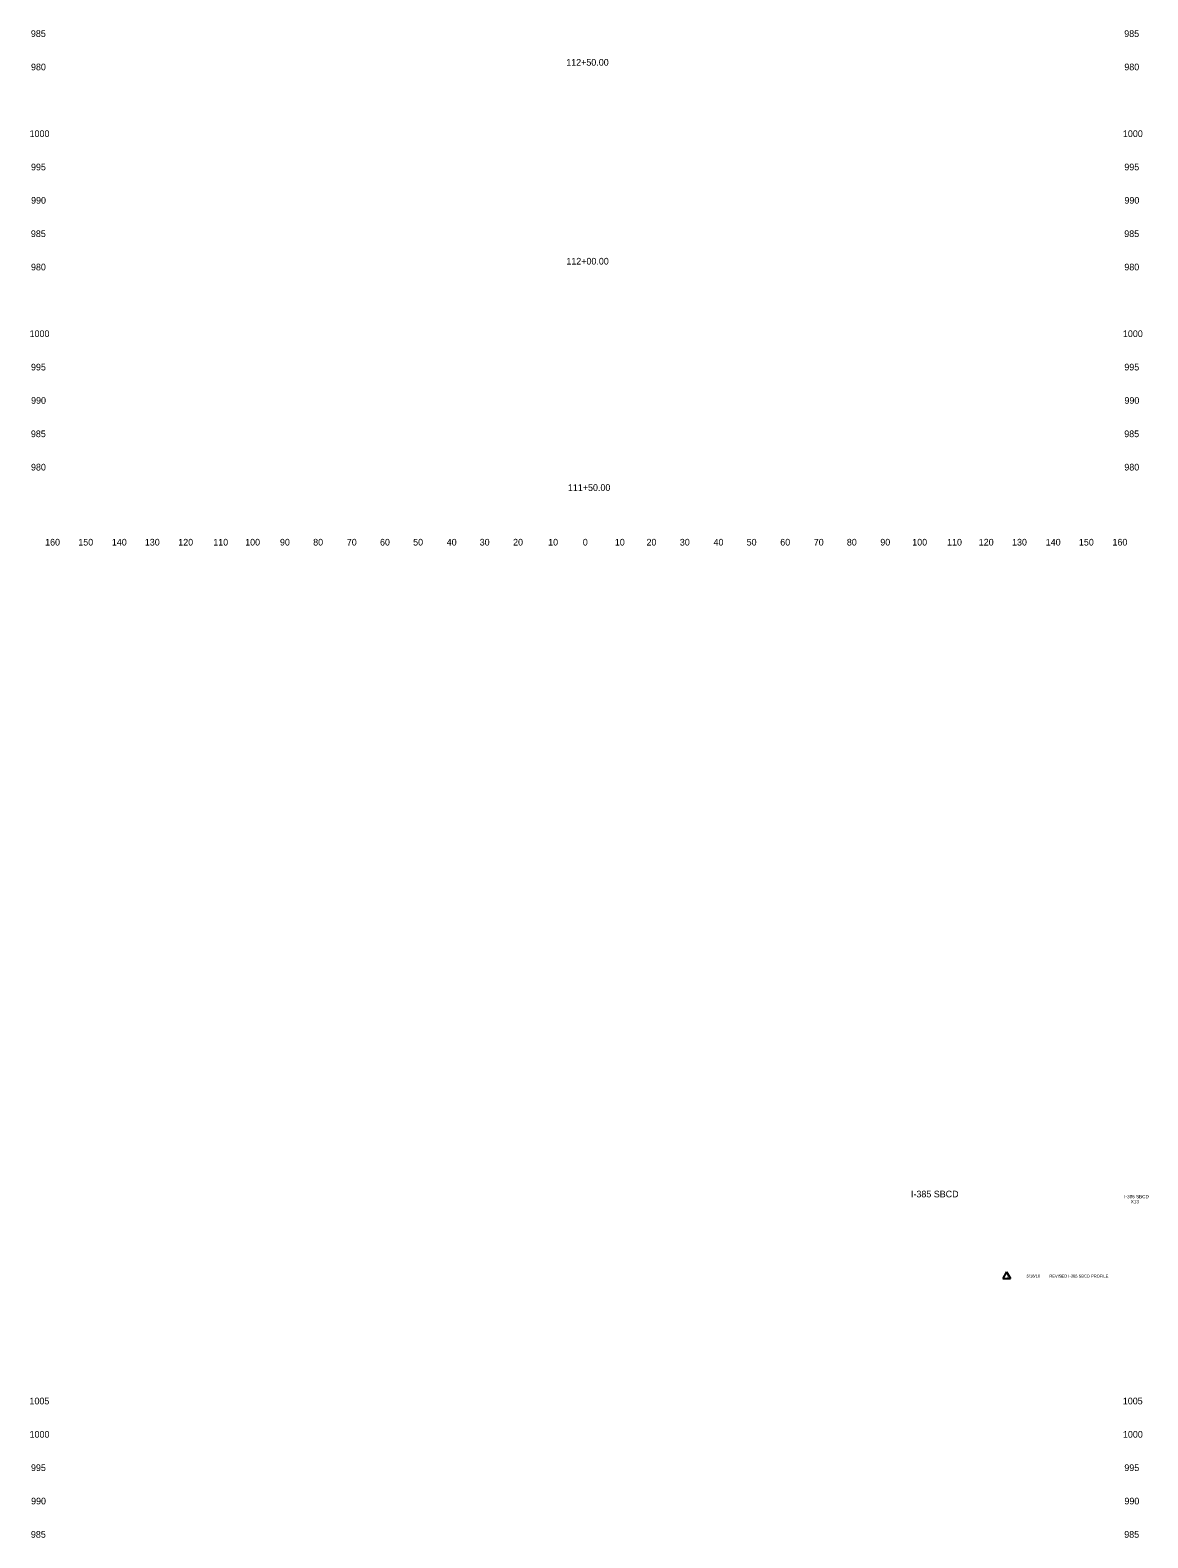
# Model space of a CAD drawing. Extents: x 4994 to 6876, y 4997 to 8804.
# Drawn here: x 5508.6 to 5843.7, y 5900 to 6352 of the extents above; entities that cross this region are included whole.
import ezdxf

# ---------------------------------------------------------------- set-up
doc = ezdxf.new("R2010")
doc.units = 0
for name, color, linetype in [('RD_SHT_ID', 7, 'Continuous'), ('RD_SHT_TX', 7, 'Continuous'), ('RD_XS_TX_Offset', 7, 'Continuous'), ('RD_XS_TX_Station', 7, 'Continuous')]:
    doc.layers.add(name, color=color, linetype=linetype)

msp = doc.modelspace()

# ---------------------------------------------------------------- linework, layer by layer
at = {"layer": 'RD_SHT_TX'}
for p, q in [((5801.37, 5979.75), (5800.23, 5977.72)), ((5800.23, 5977.72), (5802.51, 5977.72)), ((5801.37, 5979.75), (5802.51, 5977.72))]:
    msp.add_line(p, q, dxfattribs=at)

# ---------------------------------------------------------------- texts
at = {"layer": 'RD_SHT_ID'}
for s, height, p in [('I-385 SBCD', 2, (5772.69, 6002.06)), ('I-385 SBCD', 1, (5836.63, 6001.8)), ('X13', 1, (5838.57, 6000.3))]:
    msp.add_text(s, height=height, dxfattribs=at).set_placement(p)
at = {"layer": 'RD_SHT_TX'}
for s, p in [('1', (5801.37, 5978.05)), ('5/16/16', (5807.34, 5978.01)), ('REVISED I-385 SBCD PROFILE', (5814.17, 5978.01))]:
    msp.add_text(s, height=0.88, dxfattribs=at).set_placement(p)
at = {"layer": 'RD_XS_TX_Offset'}
for s, p in [('985', (5508.83, 6350)), ('985', (5836.63, 6350)), ('980', (5508.86, 6340)), ('980', (5836.66, 6340)), ('1000', (5508.44, 6320)), ('1000', (5836.24, 6320)), ('995', (5508.86, 6310)), ('995', (5836.66, 6310)), ('990', (5508.89, 6300)), ('990', (5836.69, 6300)), ('985', (5508.83, 6290)), ('985', (5836.63, 6290)), ('980', (5508.86, 6280)), ('980', (5836.66, 6280)), ('1000', (5508.44, 6260)), ('1000', (5836.24, 6260)), ('995', (5508.86, 6250)), ('995', (5836.66, 6250)), ('990', (5508.89, 6240)), ('990', (5836.69, 6240)), ('985', (5508.83, 6230)), ('985', (5836.63, 6230)), ('980', (5508.86, 6220)), ('980', (5836.66, 6220)), ('160', (5513.1, 6197.5)), ('150', (5523.04, 6197.5)), ('140', (5533.1, 6197.5)), ('130', (5542.99, 6197.5)), ('120', (5553.01, 6197.5)), ('110', (5563.51, 6197.5)), ('100', (5573.07, 6197.5)), ('90', (5583.5, 6197.5)), ('80', (5593.46, 6197.5)), ('70', (5603.54, 6197.5)), ('60', (5613.5, 6197.5)), ('50', (5623.43, 6197.5)), ('40', (5633.5, 6197.5)), ('30', (5643.39, 6197.5)), ('20', (5653.4, 6197.5)), ('10', (5663.91, 6197.5)), ('0', (5674.3, 6197.5)), ('0', (5674.3, 6197.5)), ('10', (5683.91, 6197.5)), ('20', (5693.4, 6197.5)), ('30', (5703.39, 6197.5)), ('40', (5713.5, 6197.5)), ('50', (5723.43, 6197.5)), ('60', (5733.5, 6197.5)), ('70', (5743.54, 6197.5)), ('80', (5753.46, 6197.5)), ('90', (5763.5, 6197.5)), ('100', (5773.07, 6197.5)), ('110', (5783.51, 6197.5)), ('120', (5793.01, 6197.5)), ('130', (5802.99, 6197.5)), ('140', (5813.1, 6197.5)), ('150', (5823.04, 6197.5)), ('160', (5833.1, 6197.5)), ('1005', (5508.4, 5940)), ('1005', (5836.2, 5940)), ('1000', (5508.44, 5930)), ('1000', (5836.24, 5930)), ('995', (5508.86, 5920)), ('995', (5836.66, 5920)), ('990', (5508.89, 5910)), ('990', (5836.69, 5910)), ('985', (5508.83, 5900)), ('985', (5836.63, 5900))]:
    msp.add_text(s, height=2, dxfattribs=at).set_placement(p)
at = {"layer": 'RD_XS_TX_Station'}
for s, p in [('112+50.00', (5669.34, 6341.38)), ('112+00.00', (5669.37, 6281.75)), ('111+50.00', (5669.84, 6213.88))]:
    msp.add_text(s, height=2, dxfattribs=at).set_placement(p)

doc.saveas('drawing.dxf')
